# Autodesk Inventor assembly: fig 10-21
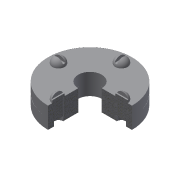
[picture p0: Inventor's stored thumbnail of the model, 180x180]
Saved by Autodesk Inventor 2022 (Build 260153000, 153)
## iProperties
Created: 2002-02
Part Number: fig 10-21
Document SubType Name: Assembly
Designer: ***
Control State: 0
Master: False
Checked Out: False
Shininess: 64.0
Angle Display Precision: 2
Document Length Units: 11269
Document Angle Units: 11279
Document Time Units: 11290
Document Mass Units: 11283
Document Length Units Precision: 3
Document Angle Units Precision: 2
Density: 0.0
Volumn: 0.0
Area: 0.0
PropertySet Name: Model Information
Author: ***
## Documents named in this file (3)
- D:\PROJECTS_2021\Resources\Part Files\c10_Inv_2021_prt\fig 10-21.iam
- D:\PROJECTS_2021\Resources\Part Files\c10_Inv_2021_prt\Screw.ipt
- D:\PROJECTS_2021\Resources\Part Files\c10_Inv_2021_prt\test.ipt
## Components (6 placed, 2 different names)
1. test:1 — Insert:1, Insert:2
2. test:2 — Insert:1
3. Screw:1 — Angle:1, Insert:2
4. Screw:11
5. Screw:12
6. Screw:13
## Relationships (3: Insert 2, Angle 1)
- Insert:1: test:1 ↔ test:2
- Angle:1: Screw:1
- Insert:2: test:1 ↔ Screw:1
